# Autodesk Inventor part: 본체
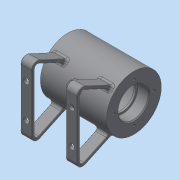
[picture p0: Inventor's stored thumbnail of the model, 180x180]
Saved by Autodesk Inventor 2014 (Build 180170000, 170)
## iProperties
Created: 2021-12
Part Number: 본체
Material: 일반
Document SubType Name: Modeling
Designer: dg
Density: 1 g/cm^3
Appearance: 기본값
Author: dg
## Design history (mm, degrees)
sketch "스케치1"
  geometry: L1 (0, 0)-(70, 0); L2 (70, 0)-(70, 29); L3 (70, 29)-(0, 29); L4 (0, 29)-(0, 0); L5 (0, 16)-(12, 16); L6 (12, 16)-(12, 14); L7 (12, 14)-(14, 14); L8 (14, 14)-(14, 21); L9 (14, 21)-(56, 21); L10 (56, 21)-(56, 14); L11 (56, 14)-(58, 14); L12 (58, 14)-(58, 16); L13 (58, 16)-(70, 16)
  constraints: 26 end point, 8 parallel, 3 perpendicular, 2 collinear, 2 horizontal alignment, 2 point on line, 1 horizontal
  dimensions: "d0" = 70 distance of L1.start L1.end; "d1" = 29 distance between parallel lines of L1 L3; "d2" = 16 distance between parallel lines of L1 L5; "d3" = 21 distance between parallel lines of L1 L9; "d4" = 14 distance between parallel lines of L1 L7; "d5" = 42 distance of L8.end L9.end; "d6" = 12 distance of L5.start L5.end; "d7" = 2 distance of L6.end L7.end
revolve "회전1" sketch "스케치1" stored, may be unused: angle "d8" = 90 deg
fillet "모깎기1" dims "d9" = 3
chamfer "모따기1" distance "d10" = 1; stored, may be unused: second distance "d11" = 2, angle "d12" = 45 deg
chamfer "모따기2" distance "d13" = 1; stored, may be unused: second distance "d14" = 2, angle "d15" = 45 deg
fillet "모깎기2" dims "d16" = 0.3
node "작업 평면2"
  node "작업 평면1"
sketch "스케치2"
  geometry: L1 (-6, -29)-(-6, 29) reference; C1 r 5 at (29, 0); 2 further points
  constraints: 1 centre point, 1 coincident, 1 horizontal alignment
  dimensions: "d19" = 35 distance from line of L1 point (29, 0); "d20" = 10 diameter of C1
extrude "돌출1" join sketch "스케치2" stored distance "d21" = 10; taper "d22" = 0 deg
hole "구멍1" diameter "d25" = 5.188; stored, may be unused: countersink angle "d29" = 90 deg, drill point angle "d31" = 118 deg; dims "d23" = 10, "d24" = 10, "d26" = 6, "d27" = 4, "d28" = 2, "d30" = 8
sketch "스케치3"
  geometry: C1 r 5 at (0, 0) reference; C2 r 1.5 at (0, 0); 1 further point
  constraints: 1 centre point, 1 coincident
  dimensions: "d32" = 3 diameter of C2
extrude "돌출2" cut sketch "스케치3" stored distance "d33" = 10; taper "d34" = 0 deg
fillet "모깎기3" dims "d35" = 1
node "작업 평면3"
sketch "스케치4"
  geometry: L1 (-22.743, -17.993)-(-40, -55); L2 (-40, -55)-(40, -55); L3 (40, -55)-(22.743, -17.993); L4 (20.574, -20.438)-(35.291, -52); L5 (35.291, -52)-(-35.291, -52); L6 (-35.291, -52)-(-20.574, -20.438); A1 r 29 centre (0, 0) between (-20.574, -20.438) and (-22.743, -17.993) reference; 2 further points
  constraints: 12 end point, 4 point on circle, 1 horizontal, 1 midpoint, 1 vertical alignment
  dimensions: "d37" = 80 distance of L2.end L1.end; "d38" = 55 distance from line of L2 point (0, 0); "d39" = 65 deg angle of L2 L1; "d40" = 65 deg angle of L2 L3; "d41" = 3 distance between parallel lines of L1 L6; "d42" = 3 distance between parallel lines of L3 L4; "d43" = 3 distance between parallel lines of L5 L2
extrude "돌출3" join sketch "스케치4" distance "d44" = 12; taper "d45" = 0 deg
node "작업 평면4"
fillet "모깎기4" dims "d46" = 6
fillet "모깎기5" dims "d47" = 3
fillet "모깎기6" dims "d48" = 0.5
fillet "모깎기7" dims "d49" = 3
fillet "모깎기8" dims "d50" = 6
sketch "스케치5"
  geometry: L1 (-0.5, 0)-(-0.5, -61.164) reference; C1 r 3 at (5.5, -12.582); C2 r 3 at (5.5, -48.582); 1 further point
  constraints: 2 centre point, 1 vertical alignment
  dimensions: "d51" = 6 diameter of C1; "d52" = 6 diameter of C2; "d53" = 6 distance from line of L1 C1.centre; "d54" = 36 distance of C2.centre C1.centre; "d55" = 18 vertical distance of point (-5.5, -30.582) C1.centre
extrude "돌출4" cut sketch "스케치5" distance "d56" = 12; taper "d57" = 0 deg
node "작업 평면5"
node "작업 평면6"
sketch "스케치6"
  geometry: L1 (0, 0)-(0, -46.155); L2 (0, 0)-(13.052, -35.861); L3 (15.342, -24.609)-(16.583, -28.018); L4 (16.583, -28.018)-(5.306, -32.122); L5 (5.306, -32.122)-(4.066, -28.714); A1 r 29 centre (0, 0) between (15.342, -24.609) and (4.066, -28.714) reference
  constraints: 10 end point, 2 perpendicular, 2 point on circle, 1 parallel, 1 vertical
  dimensions: "d58" = 20 deg angle of L1 L2; "d59" = 32 distance from line of A1.centre L4; "d61" = 6 distance between parallel lines of L2 L3; "d62" = 12 distance between parallel lines of L3 L5
extrude "돌출5" join sketch "스케치6" stored distance "d63" = 12; taper "d64" = 0 deg
fillet "모깎기9" dims "d65" = 6
hole "구멍2" diameter "d68" = 5.188; stored, may be unused: countersink angle "d72" = 90 deg, drill point angle "d74" = 118 deg; dims "d69" = 6, "d70" = 4, "d71" = 2, "d73" = 8, "d94" = 10, "d95" = 10
fillet "모깎기10" dims "d75" = 1
sketch "스케치7"
  geometry: C1 r 29 at (0, 0) reference; 1 further point
  constraints: 1 vertical alignment
  dimensions: "d76" = 21 distance of C1.centre point (0, 21)
hole "구멍3" sketch "스케치7" at (0, 21) diameter "d77" = 3.242; stored, may be unused: countersink angle "d81" = 90 deg, drill point angle "d83" = 118 deg; dims "d78" = 8, "d79" = 4, "d80" = 2, "d82" = 10
node "작업 평면7"
node "작업축2"
node "작업 평면9"
  node "작업 평면8"
node "작업 평면10"
node "작업 평면11"
node "작업 평면12"
node "작업 평면13"
sketch "스케치8"
  geometry: L1 (35, 29)-(-35, 29) reference; L2 (-35, 29)-(-35, -29) reference; 3 further points
  constraints: 1 horizontal alignment, 1 midpoint, 1 vertical alignment, 1 other
  dimensions: "d90" = 35 distance from line of point (0, 0) L2 (derived); "d91" = 29 distance from line of point (0, 0) L1 (derived)
feature "엠보싱1" sketch "스케치8" dims "d92" = 0.5, "d93" = 0
node "솔리드1"
mirror "대칭1"
mirror "대칭2"
pattern_circular "원형 패턴1" dims angle "d85" = 360 deg
mirror "대칭3"
node "작업축1"
other parameters: "d17" = 0, "d18" = 32, "d36" = -5, "d87" = 0, "d88" = 0, "d89" = 180 deg
